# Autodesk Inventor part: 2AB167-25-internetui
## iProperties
Created: 2010-10
Part Number: 2AB167-25-internetui
Document SubType Name: Modeling
Designer: Darius
Author: Darius
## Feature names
1. Base1
